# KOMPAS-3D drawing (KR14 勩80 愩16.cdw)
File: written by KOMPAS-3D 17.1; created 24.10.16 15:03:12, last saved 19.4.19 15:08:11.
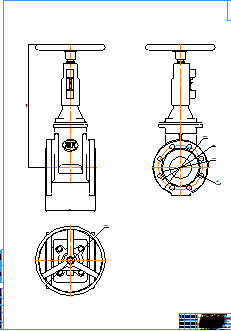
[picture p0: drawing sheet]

Sheet 1: A0, portrait

Title block, sheet 1: name: KR14 Ду80 Ру16; material: Внимание! Данный продукт является объектом авторского права ООО «Торговый Дом АДЛ». / Запрещается изменение, копирование, распространение / (в том числе путем копирования на другие сайты и ресурсы в Интернете) / или любое иное использование информации и объектов без предварительного / согласия правообладателя (ООО «Торговый Дом АДЛ»).; mass: 20,5; sheets: 1; organisation: ООО "Торговый дом АДЛ"; sheet format: A0; stored path: \\adlc.lan\data\АДЛ_ПКД\3D-модели\ADL production\Клиновые задвижки серии KR ГРАНАР\Клиновые задвижки KR14\kompas 2d\KR14 Ду80 Ру16.cdw

Views: Вид 1
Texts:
  Klimkovich
  ADL
Dimensions and other numbers on the sheet: 180; 441; 1:1; 1; 20,5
